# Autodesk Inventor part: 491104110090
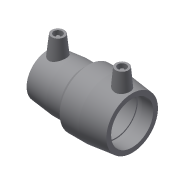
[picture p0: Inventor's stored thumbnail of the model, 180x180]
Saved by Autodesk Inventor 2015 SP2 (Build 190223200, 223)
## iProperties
Created: 2017-06
Part Number: 491104110090
Material: Generic
Description: PLASSON REDUCING COUPLER 110-90
Document SubType Name: Modeling
Designer: KIM
Mass: 54.8237 g
Surface Area: 155.252 cm^2
Volume: 54.8237 cm^3
Density: 1 g/cm^3
Appearance: Default
Author: KIM
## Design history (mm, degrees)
derived "491104.ipt"
feature "Solid1::491104.ipt"
tag "TaggingFeature1"
body "Solid1"
other parameters: "L_" = 161, "L_2" = 72, "D_1" = 116, "A_1" = 74, "d_2" = 12, "L_1" = 78, "A_" = 84, "D_" = 139, "d0" = 161, "d2" = 116, "d3" = 72, "d4" = 43.2, "d5" = 104.4, "d8" = 168 deg, "d10" = 28.8, "d11" = 9.6, "d13" = 161, "d14" = 17.6296, "d15" = 72, "d19" = 3.6, "d20" = 168 deg, "d22" = 108.92847, "d25" = 135 deg, "d29" = 74, "d30" = 15, "d31" = 64.4, "d34" = 6 deg, "d35" = 15, "d38" = 24.5, "d39" = 5 deg, "d41" = 4, "d42" = 14, "d43" = 0, "d45" = 4, "d46" = 14, "d47" = 0, "d48" = 116, "d50" = 139, "d52" = 81, "d53" = 31.2, "d54" = 10.4, "d55" = 168 deg, "d56" = 46.8, "d57" = 78, "d58" = 125.1, "d59" = 3.6, "d60" = 135 deg, "d61" = 84, "d62" = 15, "d64" = 4, "d66" = 5 deg, "d67" = 14, "d68" = 0, "d69" = 64.4, "d70" = 116, "d71" = 139, "d73" = 130.66, "d76" = 3.6, "d77" = 168 deg, "d79" = 3.6, "d80" = 78, "d81" = 81, "d82" = 109.04, "d83" = 120 deg, "d88" = 15, "d89" = 23.5, "d90" = 5 deg, "d92" = 4, "d93" = 14, "d94" = 0, "d95" = 3, "d96" = 0, "d97" = 3, "d98" = 0, "d99" = 20.88, "d100" = 5.22, "d101" = 105.7688, "d102" = 20 deg, "d103" = 22.62, "d104" = 5.655, "d105" = 126.7402, "d106" = 3.60705, "d107" = 3, "d108" = 0, "d109" = 3, "d110" = 0
